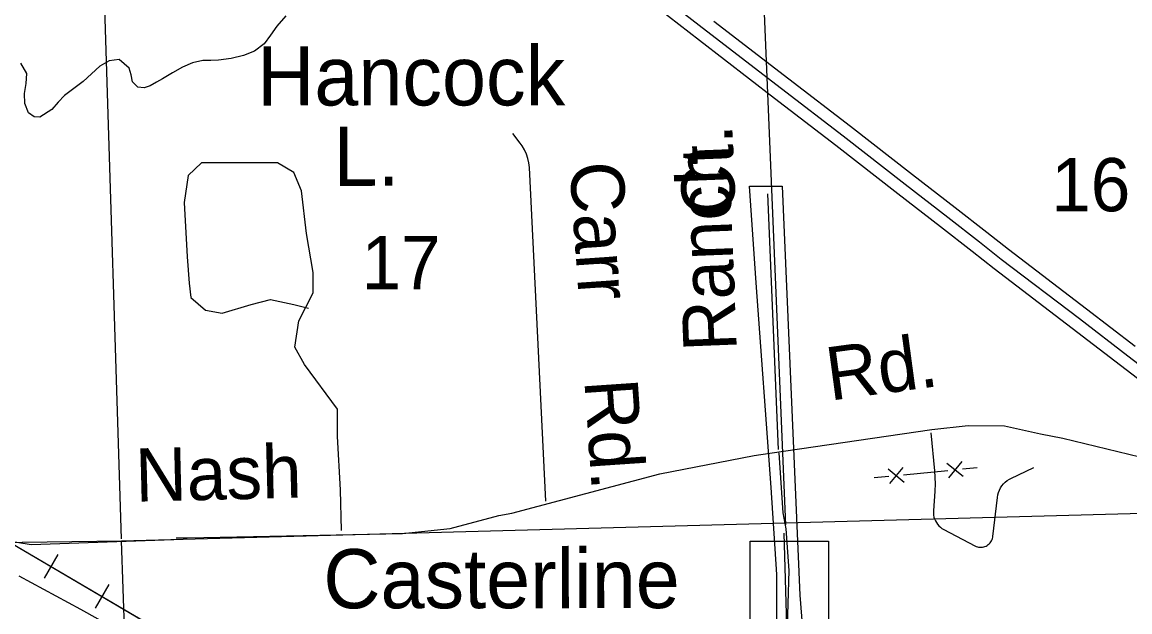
# Model space of a CAD drawing. Extents: x 2480962 to 2688785, y 277103 to 599240.
# Drawn here: x 2522427 to 2531781, y 447355 to 452337 of the extents above; entities that cross this region are included whole.
import ezdxf

# ---------------------------------------------------------------- set-up
doc = ezdxf.new("R2010")
doc.units = 0
for name, color, linetype in [('Interstate Divided Highway Outline and Fill', 7, 'Continuous'), ('Interstate Highway Center Lines', 7, 'Continuous'), ('Lakes and Ponds', 7, 'Continuous'), ('Lakes and Ponds Text', 7, 'Continuous'), ('Level 31', 7, 'Continuous'), ('Level 36', 7, 'Continuous'), ('Local Roads Paved', 7, 'Continuous'), ('Local Roads Related Text', 7, 'Continuous'), ('Local Roads Unimproved', 7, 'Continuous'), ('Railroads', 7, 'Continuous'), ('Section Lines', 7, 'Continuous'), ('Swamps', 7, 'Continuous'), ('Uninventoried Roads and Features', 7, 'Continuous')]:
    doc.layers.add(name, color=color, linetype=linetype)

msp = doc.modelspace()

# ---------------------------------------------------------------- linework, layer by layer
at = {"layer": 'Interstate Divided Highway Outline and Fill'}
for points in [[(2527797.822, 452456.024), (2528145.333, 452183.212), (2528779.192, 451695.628), (2529298.773, 451296.2), (2529821.632, 450890.254), (2530182.114, 450610.961), (2530448.131, 450403.338), (2530633.712, 450256.827), (2531293.642, 449752.94), (2531702.923, 449437.858), (2532144.577, 449100.122)], [(2531824.67, 449596.533), (2531415.33, 449911.659), (2530756.371, 450414.806), (2530571.624, 450560.659), (2530304.888, 450768.843), (2529944.204, 451048.292), (2529421.047, 451454.469), (2528901.11, 451854.171), (2528268.057, 452341.135)]]:
    msp.add_lwpolyline(points, dxfattribs=at)
at = {"layer": 'Interstate Highway Center Lines'}
msp.add_lwpolyline([(2527859.106, 452535.047), (2528206.695, 452262.174), (2528840.151, 451774.899), (2529359.91, 451375.335), (2529882.918, 450969.273), (2530243.501, 450689.902), (2530509.877, 450481.998), (2530695.042, 450335.816), (2531354.486, 449832.3), (2531763.796, 449517.196), (2532205.592, 449179.352)], dxfattribs=at)
at = {"layer": 'Lakes and Ponds'}
msp.add_lwpolyline([(2524652.826, 452391.541), (2524577.552, 452302.61), (2524524.916, 452227.412), (2524469.083, 452152.971), (2524388.897, 452093.05), (2524296.339, 452055.003), (2524191.509, 452029.481), (2524085.648, 452014.435), (2524019.571, 452014.13), (2523953.581, 452012.164), (2523864.114, 451992.207), (2523780.133, 451956.405), (2523696.256, 451907.532), (2523612.673, 451858.527), (2523560.4, 451828.463), (2523507.988, 451798.672), (2523455.955, 451780.511), (2523402.51, 451786.303), (2523359.455, 451833.061), (2523346.725, 451890.85), (2523331.104, 451948.681), (2523245.347, 452021.093), (2523161.629, 452011.218), (2523082.464, 451965.515), (2523011.881, 451900.304), (2522941.946, 451836.435), (2522863.407, 451777.448), (2522785.403, 451717.634), (2522730.892, 451660.051), (2522676.405, 451599.652), (2522577.091, 451534.613), (2522528.025, 451535.537), (2522481.386, 451569.909), (2522449.355, 451650.939), (2522446.958, 451732.924), (2522460.832, 451817.631), (2522465.27, 451902.123), (2522415.496, 451990.175)], dxfattribs=at)
at = {"layer": 'Level 31'}
for points in [[(2528568.139, 450950.859), (2528844.418, 450950.859), (2528994.069, 447497.368), (2529028.604, 447071.438), (2529120.697, 446449.809), (2529120.697, 445551.902), (2529109.186, 444769.11), (2529040.116, 444734.576), (2528890.464, 444653.994), (2528855.93, 445287.134), (2528798.371, 446334.693), (2528798.371, 446921.786), (2528798.371, 447670.043), (2528752.325, 448406.787), (2528625.697, 450133.533)], [(2528573.305, 447952.327), (2529236.295, 447952.327), (2529236.295, 447288.894), (2528573.305, 447288.894)]]:
    msp.add_lwpolyline(points, close=True, dxfattribs=at)
at = {"layer": 'Local Roads Paved'}
for p, q in [((2526633.095, 451315.413), (2526570.726, 451395.656)), ((2526849.262, 448288.71), (2526710.404, 451109.679)), ((2528741.625, 448696.634), (2530109.596, 448895.86)), ((2531215.849, 448821.205), (2531864.901, 448665.403)), ((2526563.055, 448187.83), (2527811.029, 448521.089)), ((2523727.845, 447980.768), (2523821.39, 447979.725)), ((2523821.39, 447979.725), (2525638.084, 448017.73))]:
    msp.add_line(p, q, dxfattribs=at)
for points in [[(2526710.404, 451109.679), (2526706.127, 451148.208), (2526697.846, 451186.079), (2526685.652, 451222.875), (2526669.679, 451258.196), (2526650.101, 451291.655), (2526633.095, 451315.413)], [(2525122.81, 448042.318), (2525114.614, 448386.555), (2525090.026, 448837.343), (2525090.026, 449066.834), (2524811.357, 449443.856), (2524729.396, 449591.387), (2524762.18, 449812.682), (2524885.122, 450050.37), (2524885.122, 450222.489), (2524827.749, 450550.334), (2524786.769, 450910.964), (2524721.2, 451066.691), (2524581.865, 451148.652), (2524163.863, 451148.652), (2523942.567, 451148.652), (2523827.821, 451042.102), (2523795.037, 450812.61), (2523819.625, 450353.627), (2523836.017, 450132.332), (2523852.41, 450009.39), (2523975.352, 449902.84), (2524114.686, 449878.251), (2524360.57, 449952.017), (2524524.492, 449992.997), (2524721.2, 449952.017), (2524844.142, 449919.232)], [(2530109.596, 448895.86), (2530413.897, 448930.081), (2530720.992, 448926.252), (2531026.082, 448860.18), (2531215.849, 448821.205)], [(2527811.029, 448521.089), (2528608.858, 448675.185), (2528741.625, 448696.634)], [(2529041.591, 446147.342), (2529005.993, 446704.845), (2528954.691, 446892.952), (2528911.94, 447038.307), (2528886.289, 447140.911), (2528903.39, 447705.231), (2528877.739, 448055.794), (2528852.088, 448192.599), (2528817.886, 448697.067)], [(2519885.525, 448400.86), (2519956.551, 448599.734), (2520823.073, 448535.81), (2521050.358, 448493.195), (2521540.44, 448265.91), (2522051.83, 448067.036), (2522279.114, 447960.497), (2522502.591, 447925.151), (2523706.854, 447967.456)], [(2525638.084, 448017.73), (2526042.213, 448059.099), (2526451.421, 448168.221), (2526563.055, 448187.83)], [(2531584.991, 436471.544), (2531655.475, 437408.984), (2531676.62, 437909.422), (2531648.427, 438374.618), (2531627.281, 439368.445), (2531613.185, 440094.432), (2531606.136, 440707.645), (2531549.749, 442695.3), (2531535.652, 443893.531), (2531514.507, 443964.015), (2530992.924, 444119.081), (2530471.34, 444274.146), (2529047.559, 444668.857), (2528018.49, 444943.746), (2527405.277, 445127.005), (2527003.517, 445246.828), (2526531.273, 445451.232), (2526171.804, 445648.588), (2525410.574, 446036.251), (2524938.33, 446311.139), (2524423.795, 446564.883), (2523387.678, 447114.659), (2522922.482, 447375.451), (2522400.899, 447657.388)]]:
    msp.add_lwpolyline(points, dxfattribs=at)
at = {"layer": 'Local Roads Unimproved'}
msp.add_line((2528814.892, 448727.652), (2528723.833, 450885.947), dxfattribs=at)
at = {"layer": 'Railroads'}
for p, q in [((2522298.813, 447957.824), (2525353.968, 446161.924)), ((2522728.172, 447838.833), (2522611.618, 447640.552)), ((2522728.172, 447838.833), (2522611.618, 447640.552)), ((2523159.216, 447585.454), (2523042.662, 447387.173)), ((2523159.216, 447585.454), (2523042.662, 447387.173))]:
    msp.add_line(p, q, dxfattribs=at)
msp.add_lwpolyline([(2504457.222, 450568.165), (2520855.254, 448452.084), (2521247.687, 448380.391), (2521630.476, 448268.069), (2521999.426, 448116.348), (2522298.814, 447957.824), (2522298.813, 447957.824), (2525353.968, 446161.924), (2526001.076, 445825.806), (2526679.773, 445559.173), (2527030.858, 445452.248), (2544991.828, 440495.215), (2545784.966, 440320.413), (2546592.032, 440229.478), (2546781.298, 440220.456), (2557380.702, 439844.874), (2557380.701, 439844.874), (2557789.911, 439808.861), (2557931.671, 439786.211), (2566903.276, 438184.008)], dxfattribs=at)
msp.add_lwpolyline([(2504457.222, 450568.165), (2520855.254, 448452.084), (2521247.687, 448380.391), (2521630.476, 448268.069), (2521999.426, 448116.348), (2522298.814, 447957.824), (2522298.813, 447957.824), (2525353.968, 446161.924), (2526001.076, 445825.806), (2526679.773, 445559.173), (2527030.858, 445452.248), (2544991.828, 440495.215), (2545784.966, 440320.413), (2546592.032, 440229.478), (2546781.298, 440220.456), (2557380.702, 439844.874), (2557380.701, 439844.874), (2557789.911, 439808.861), (2557931.671, 439786.211), (2566903.276, 438184.008)], dxfattribs=at)
at = {"layer": 'Section Lines'}
for p, q in [((2528647.258, 453463.194), (2528873.171, 448089.639)), ((2523265.143, 447970.771), (2523098.557, 453344.259)), ((2523265.661, 447954.029), (2533950.898, 448244.798)), ((2517753.341, 447881.144), (2523265.661, 447954.029)), ((2523443.266, 442746.165), (2523265.661, 447954.029)), ((2528859.348, 448018.639), (2529002.314, 442841.198))]:
    msp.add_line(p, q, dxfattribs=at)
at = {"layer": 'Swamps'}
msp.add_line((2528859.347, 448018.639), (2528859.348, 448018.639), dxfattribs=at)
at = {"layer": 'Uninventoried Roads and Features'}
for p, q in [((2530100.06, 448867.807), (2530130.706, 448546.802)), ((2530236.407, 448612.473), (2530373.032, 448500.296)), ((2530360.808, 448624.697), (2530248.631, 448488.071)), ((2529738.802, 448563.576), (2529875.428, 448451.399)), ((2529863.203, 448575.8), (2529751.027, 448439.175)), ((2529869.316, 448513.599), (2530242.519, 448550.272)), ((2530366.92, 448562.496), (2530491.321, 448574.72)), ((2530775.79, 448481.804), (2530969.83, 448574.564)), ((2529620.513, 448489.151), (2529744.914, 448501.375)), ((2530133.075, 448375.417), (2530121.714, 448207.473)), ((2530624.29, 447992.372), (2530662.089, 448322.354)), ((2530209.267, 448050.857), (2530472.95, 447912.325))]:
    msp.add_line(p, q, dxfattribs=at)
for points in [[(2530130.706, 448546.802), (2530135.431, 448436.532), (2530133.075, 448375.417)], [(2530662.089, 448322.354), (2530665.596, 448343.23), (2530671.265, 448363.626), (2530679.035, 448383.317), (2530688.822, 448402.089), (2530700.516, 448419.734), (2530713.991, 448436.061), (2530729.098, 448450.889), (2530745.673, 448464.057), (2530763.534, 448475.42), (2530775.79, 448481.804)], [(2530121.714, 448207.473), (2530121.453, 448190.269), (2530122.991, 448173.132), (2530126.312, 448156.249), (2530131.381, 448139.806), (2530138.139, 448123.983), (2530146.515, 448108.953), (2530156.416, 448094.881), (2530167.733, 448081.921), (2530180.343, 448070.215), (2530194.108, 448059.891), (2530208.876, 448051.062), (2530209.267, 448050.857)], [(2530472.95, 447912.325), (2530482.816, 447907.784), (2530493.102, 447904.299), (2530503.696, 447901.908), (2530514.482, 447900.638), (2530525.342, 447900.503), (2530536.156, 447901.503), (2530546.807, 447903.628), (2530557.177, 447906.855), (2530567.152, 447911.148), (2530576.625, 447916.461), (2530585.491, 447922.734), (2530593.652, 447929.9), (2530601.019, 447937.88), (2530607.513, 447946.586), (2530613.06, 447955.923), (2530617.601, 447965.789), (2530621.086, 447976.075), (2530623.477, 447986.67), (2530624.29, 447992.372)]]:
    msp.add_lwpolyline(points, dxfattribs=at)

# ---------------------------------------------------------------- texts
at = {"layer": 'Lakes and Ponds Text'}
for s, rotation, p in [('Hancock', 0.0289361, (2524411.304, 451632.558)), ('L.', 0.0289444, (2525056.896, 450953.84)), ('Casterline', 0.0336139, (2524970.126, 447384.934))]:
    msp.add_text(s, height=500, rotation=rotation, dxfattribs=at).set_placement(p)
at = {"layer": 'Level 36'}
for s, p in [('16', (2531115.354, 450738.911)), ('17', (2525291.58, 450080.853))]:
    msp.add_text(s, height=450, rotation=359.9795056, dxfattribs=at).set_placement(p)
at = {"layer": 'Local Roads Related Text'}
for s, rotation, p in [('Rd.', 7.6604722, (2529248.287, 449138.428)), ('Nash', 1.4306167, (2523386.934, 448285.379))]:
    msp.add_text(s, height=450, rotation=rotation, dxfattribs=at).set_placement(p)
at = {"layer": 'Uninventoried Roads and Features'}
for s, rotation, p in [('Ct.', 92.2462889, (2528452.615, 450708.759)), ('Ranch', 92.2462889, (2528461.968, 449564.268)), ('Carr    Rd.', 273.9009861, (2527048.894, 451144.206))]:
    msp.add_text(s, height=450, rotation=rotation, dxfattribs=at).set_placement(p)

doc.saveas('drawing.dxf')
